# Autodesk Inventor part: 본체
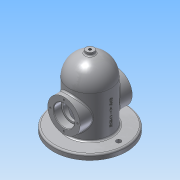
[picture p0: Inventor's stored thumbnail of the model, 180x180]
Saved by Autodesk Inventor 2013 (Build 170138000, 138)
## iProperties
Created: 2019-11
Part Number: 본체
Material: 알루미늄 6061
Document SubType Name: Modeling
Designer: Administrator
Density: 2.71 g/cm^3
Mass: 1110.22 g
Surface Area: 883.263 cm^2
Volume: 409.674 cm^3
Author: Administrator
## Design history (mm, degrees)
sketch "스케치1"
  geometry: C1 r 70 at (0, 0); 1 further point
  constraints: 1 centre point, 1 coincident
  dimensions: "d0" = 140 diameter of C1
extrude "돌출1" new body sketch "스케치1" distance "d1" = 10; taper "d2" = 0 deg
sketch "스케치2"
  geometry: C1 r 70 at (0, 0) reference; C2 r 40 at (0, 0)
  constraints: 1 centre point, 1 coincident
  dimensions: "d3" = 80 diameter of C2
extrude "돌출2" join sketch "스케치2" distance "d4" = 80; taper "d5" = 0 deg
sketch "스케치3"
  geometry: L1 (-70, 0)-(-70, 10) reference; L2 (-70, 10)-(-40, 10) reference; L3 (-40, 10)-(-40, 90) reference; L4 (-40, 90)-(40, 90) reference; L5 (40, 90)-(40, 10) reference; L6 (40, 10)-(70, 10) reference; L7 (70, 10)-(70, 0) reference; L8 (70, 0)-(-70, 0) reference; A1 r 40 centre (0, 90) between (40, 90) and (-40, 90); 1 further point
  constraints: 2 end point, 2 point on circle, 1 centre point, 1 midpoint
revolve "회전1" sketch "스케치3" stored, may be unused: angle "d6" = 90 deg
node "작업 평면1"
sketch "스케치4"
  geometry: L1 (70, 10)-(-70, 10) reference; L2 (-70, 0)-(70, 0) reference; L3 (40, 90)-(-40, 90) reference; L4 (-40, 10)-(40, 10) reference; C1 r 31 at (0, 50); 2 further points
  constraints: 1 centre point, 1 midpoint, 1 vertical alignment
  dimensions: "d8" = 62 diameter of C1; "d10" = 50 distance from line of C1.centre L2
extrude "돌출3" join sketch "스케치4" stored distance "d11" = 90; taper "d12" = 0 deg
sketch "스케치5"
  geometry: C1 r 31 at (0, 0) reference; C2 r 16.5 at (0, 0); 1 further point
  constraints: 1 centre point, 1 coincident
  dimensions: "d13" = 33 diameter of C2
extrude "돌출4" cut sketch "스케치5" stored distance "d14" = 90; taper "d15" = 0 deg
sketch "스케치7"
  geometry: C1 r 16.5 at (0, 0) reference; C2 r 31 at (0, 0) reference; C3 r 20 at (0, 0); 1 further point
  constraints: 1 centre point, 1 coincident
  dimensions: "d16" = 40 diameter of C3
extrude "돌출5" cut sketch "스케치7" distance "d17" = 15; taper "d18" = 0 deg
sketch "스케치8"
  geometry: C1 r 16.5 at (0, 0) reference; C2 r 31 at (0, 0) reference; C3 r 20 at (0, 0); 1 further point
  constraints: 1 centre point, 1 coincident
  dimensions: "d19" = 40 diameter of C3
extrude "돌출6" cut sketch "스케치8" distance "d20" = 15; taper "d21" = 0 deg
chamfer "모따기1" distance "d22" = 1; stored, may be unused: second distance "d23" = 2, angle "d24" = 45 deg
fillet "모깎기1" dims "d25" = 0.3
sketch "스케치9"
  geometry: L1 (35, 69.7)-(35, 66.5) reference; L2 (35, 66.5)-(-35, 66.5) reference; L3 (-35, 66.5)-(-35, 69.7) reference; L4 (-35.3, 70)-(-49, 70) reference; L5 (-49, 70)-(-50, 71) reference; L6 (-50, 71)-(-50, 81) reference; L7 (-50, 81)-(-40, 81) reference; L8 (-40, 81)-(-40, 90) reference; L9 (40, 90)-(40, 81) reference; L10 (40, 81)-(50, 81) reference; L11 (50, 81)-(50, 71) reference; L12 (50, 71)-(49, 70) reference; L13 (49, 70)-(35.3, 70) reference; L14 (-70, 0)-(-70, 10) reference; L15 (-70, 10)-(-40, 10) reference; L16 (-40, 10)-(-40, 19) reference; L17 (-40, 19)-(-50, 19) reference; L18 (-50, 19)-(-50, 29) reference; L19 (-50, 29)-(-49, 30) reference; L20 (-49, 30)-(-35.3, 30) reference; L21 (-35, 30.3)-(-35, 33.5) reference; L22 (-35, 33.5)-(35, 33.5) reference; L23 (35, 33.5)-(35, 30.3) reference; L24 (35.3, 30)-(49, 30) reference; L25 (49, 30)-(50, 29) reference; L26 (50, 29)-(50, 19) reference; L27 (50, 19)-(40, 19) reference; L28 (40, 19)-(40, 10) reference; L29 (40, 10)-(70, 10) reference; L30 (70, 10)-(70, 0) reference; L31 (70, 0)-(-70, 0) reference; L32 (0, 0)-(-30, 0); L33 (-30, 0)-(-30, 90); L34 (-30, 90)-(0, 90); L35 (0, 90)-(0, 0); A1 r 0.3 centre (35.3, 69.7) between (35.3, 70) and (35, 69.7) reference; A2 r 0.3 centre (-35.3, 69.7) between (-35, 69.7) and (-35.3, 70) reference; A3 r 40 centre (0, 90) between (40, 90) and (0, 130) reference; A4 r 40 centre (0, 90) between (0, 130) and (-40, 90) reference; A5 r 0.3 centre (-35.3, 30.3) between (-35.3, 30) and (-35, 30.3) reference; A6 r 0.3 centre (35.3, 30.3) between (35, 30.3) and (35.3, 30) reference
  constraints: 8 end point, 2 vertical, 1 horizontal, 1 point on line
  dimensions: "d26" = 90 distance of L34.end L32.start; "d27" = 60 diameter of L33 L35
revolve "회전2" sketch "스케치9" stored, may be unused: angle "d28" = 90 deg
sketch "스케치10"
  geometry: L1 (35, 69.7)-(35, 66.5) reference; L2 (35, 66.5)-(30, 66.5) reference; L3 (30, 66.5)-(30, 90) reference; L4 (30, 90)-(-30, 90) reference; L5 (-30, 90)-(-30, 66.5) reference; L6 (-30, 66.5)-(-35, 66.5) reference; L7 (-35, 66.5)-(-35, 69.7) reference; L8 (-35.3, 70)-(-49, 70) reference; L9 (-49, 70)-(-50, 71) reference; L10 (-50, 71)-(-50, 81) reference; L11 (-50, 81)-(-40, 81) reference; L12 (-40, 81)-(-40, 90) reference; L13 (40, 90)-(40, 81) reference; L14 (40, 81)-(50, 81) reference; L15 (50, 81)-(50, 71) reference; L16 (50, 71)-(49, 70) reference; L17 (49, 70)-(35.3, 70) reference; L18 (70, 10)-(70, 0) reference; L19 (70, 0)-(30, 0) reference; L20 (30, 0)-(30, 33.5) reference; L21 (30, 33.5)-(35, 33.5) reference; L22 (35, 33.5)-(35, 30.3) reference; L23 (35.3, 30)-(49, 30) reference; L24 (49, 30)-(50, 29) reference; L25 (50, 29)-(50, 19) reference; L26 (50, 19)-(40, 19) reference; L27 (40, 19)-(40, 10) reference; L28 (40, 10)-(70, 10) reference; L29 (-70, 0)-(-70, 10) reference; L30 (-70, 10)-(-40, 10) reference; L31 (-40, 10)-(-40, 19) reference; L32 (-40, 19)-(-50, 19) reference; L33 (-50, 19)-(-50, 29) reference; L34 (-50, 29)-(-49, 30) reference; L35 (-49, 30)-(-35.3, 30) reference; L36 (-35, 30.3)-(-35, 33.5) reference; L37 (-35, 33.5)-(-30, 33.5) reference; L38 (-30, 33.5)-(-30, 0) reference; L39 (-30, 0)-(-70, 0) reference; A1 r 0.3 centre (35.3, 69.7) between (35.3, 70) and (35, 69.7) reference; A2 r 0.3 centre (-35.3, 69.7) between (-35, 69.7) and (-35.3, 70) reference; A3 r 40 centre (0, 90) between (40, 90) and (0, 130) reference; A4 r 40 centre (0, 90) between (0, 130) and (-40, 90) reference; A5 r 0.3 centre (35.3, 30.3) between (35, 30.3) and (35.3, 30) reference; A6 r 0.3 centre (-35.3, 30.3) between (-35.3, 30) and (-35, 30.3) reference; A7 r 30 centre (0, 90) between (30, 90) and (-30, 90); 1 further point
  constraints: 2 end point, 2 point on circle, 1 centre point, 1 coincident, 1 midpoint
revolve "회전3" sketch "스케치10" stored, may be unused: angle "d29" = 90 deg
node "작업 평면2"
sketch "스케치11"
  geometry: C1 r 7.5 at (0, 0); 1 further point
  constraints: 1 centre point, 1 coincident
  dimensions: "d31" = 15 diameter of C1
extrude "돌출7" join sketch "스케치11" stored distance "d33" = 15; taper "d34" = 0 deg
sketch "스케치12"
  geometry: C1 r 7.5 at (0, 0) reference
hole "구멍1" sketch "스케치12" at (0, 0) diameter "d35" = 5.188; stored, may be unused: countersink angle "d39" = 90 deg, drill point angle "d41" = 118 deg; dims "d36" = 6, "d37" = 4, "d38" = 2, "d40" = 20.5
fillet "모깎기2" dims "d42" = 3
fillet "모깎기3" dims "d43" = 3
sketch "스케치14" dims "d46" = 110
  geometry: C1 r 43 at (0, 0) reference; C2 r 4.5 at (0, 55); 1 further point
  constraints: 2 vertical alignment, 1 centre point, 1 coincident, 2 other
  dimensions: "d47" = 9 diameter of C2
extrude "돌출8" cut sketch "스케치14" stored distance "d48" = 15; taper "d49" = 0 deg
sketch "스케치15" dims "d50" = 52
  geometry: C1 r 21 at (0, 0) reference; 3 further points
  constraints: 2 horizontal alignment, 1 coincident, 2 other
hole "구멍2" sketch "스케치15" at (26, 0) diameter "d51" = 3.242; stored, may be unused: countersink angle "d55" = 90 deg, drill point angle "d57" = 118 deg; dims "d52" = 8, "d53" = 4, "d54" = 2, "d56" = 10
node "작업 평면3"
sketch "스케치16"
  geometry: L1 (0, 3)-(0, 80) reference; L2 (-53.749, 0)-(-15.78, 0) reference; L3 (-57.446, -10)-(-57.446, -3) reference; L4 (57.446, -10)-(-57.446, -10) reference; L5 (57.446, -3)-(57.446, -10) reference; L6 (15.78, 0)-(53.749, 0) reference; 2 further points
  constraints: 1 vertical alignment, 5 other
  dimensions: "d61" = 50 distance from line of point (0, 40) L4
feature "엠보싱1" sketch "스케치16" dims "d62" = 0.5, "d63" = 0
node "솔리드1"
mirror "대칭1"
mirror "대칭2"
pattern_circular "원형 패턴1" dims angle "d59" = 360 deg
mirror "대칭3"
node "투영된 루프1"
node "투영된 루프2"
node "절단 모서리 투영1"
node "절단 모서리 투영3"
node "절단 모서리 투영4"
node "절단 모서리 투영5"
other parameters: "d30" = -135
